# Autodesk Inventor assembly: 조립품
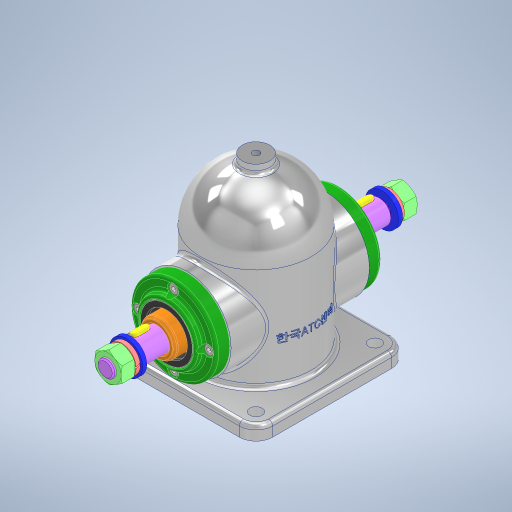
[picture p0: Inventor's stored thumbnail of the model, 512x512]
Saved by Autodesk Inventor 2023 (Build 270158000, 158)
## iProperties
Created: 2025-04
Part Number: 조립품
Document SubType Name: Assembly
Designer: ADMIN_PC
Author: ADMIN_PC
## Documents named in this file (14)
- C:\Users\ADMIN_PC\Desktop\750406V1013\조립품.iam
- C:\Users\ADMIN_PC\Desktop\750406V1013\본체.ipt
- C:\Users\ADMIN_PC\Desktop\750406V1013\750406V1013\깊은 홈 볼 베어링 6203.ipt
- C:\Users\ADMIN_PC\Desktop\750406V1013\750406V1013\축.ipt
- C:\Users\ADMIN_PC\Desktop\750406V1013\750406V1013\커버.ipt
- C:\Users\ADMIN_PC\Desktop\750406V1013\750406V1013\오일 실 26 38 8.ipt
- C:\Users\ADMIN_PC\Desktop\750406V1013\750406V1013\평행 키 5x5x12.ipt
- C:\Users\ADMIN_PC\Desktop\750406V1013\750406V1013\V 벨트 풀리.ipt
- C:\Users\ADMIN_PC\Desktop\750406V1013\750406V1013\칼라.ipt
- C:\Users\ADMIN_PC\Desktop\750406V1013\750406V1013\스퍼기어.ipt
- C:\Users\ADMIN_PC\Desktop\750406V1013\750406V1013\평와셔 M12.ipt
- C:\Users\ADMIN_PC\Desktop\750406V1013\750406V1013\스프링 와셔 M12.ipt
- C:\Users\ADMIN_PC\Desktop\750406V1013\750406V1013\6각 너트 M12x1.ipt
- C:\Users\ADMIN_PC\Desktop\750406V1013\750406V1013\6각 구멍붙이 볼트 M4x12.ipt
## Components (11 placed, 3 different names)
1. V 벨트 풀리:1
2. 6각 너트 M12x1:1
3. 6각 너트 M12x1:2
4. 6각 구멍붙이 볼트 M4x12:1
5. 6각 구멍붙이 볼트 M4x12:2
6. 6각 구멍붙이 볼트 M4x12:3
7. 6각 구멍붙이 볼트 M4x12:4
8. 6각 구멍붙이 볼트 M4x12:5
9. 6각 구멍붙이 볼트 M4x12:6
10. 6각 구멍붙이 볼트 M4x12:7
11. 6각 구멍붙이 볼트 M4x12:8
